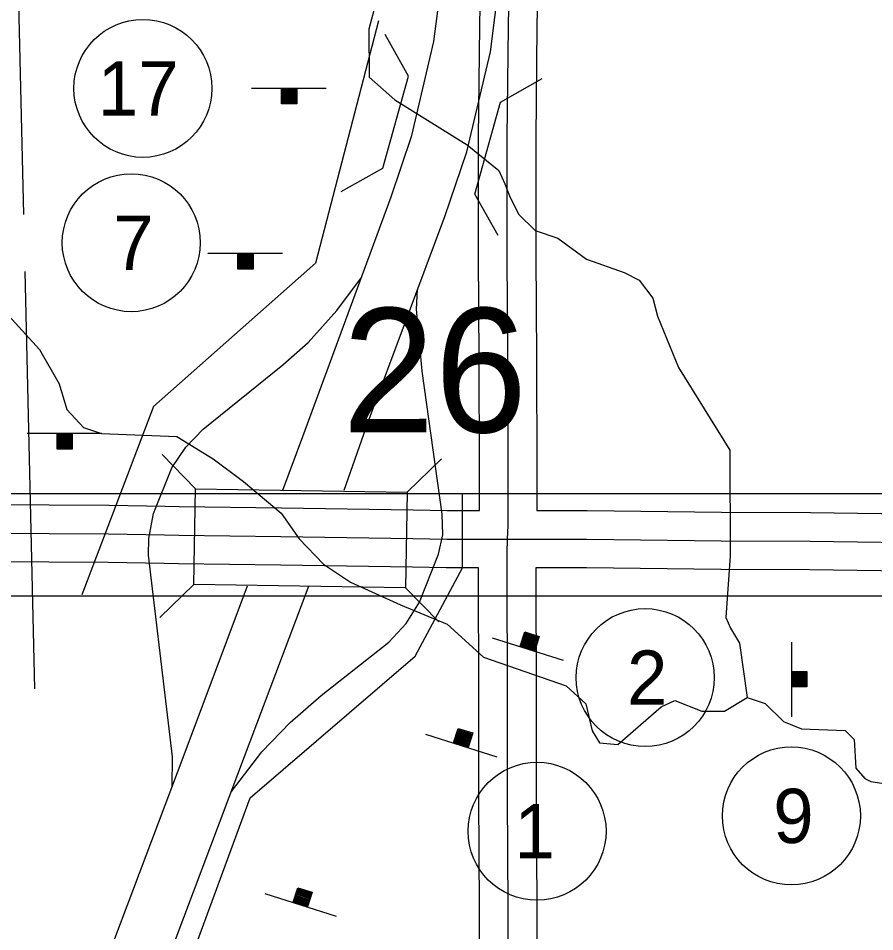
# Model space of a CAD drawing. Extents: x -2251611 to -2054719, y -2227156 to -2099355.
# Drawn here: x -2135345 to -2130609, y -2126976 to -2121927 of the extents above; entities that cross this region are included whole.
import ezdxf

# ---------------------------------------------------------------- set-up
doc = ezdxf.new("R2010")
doc.units = 0
for name, color, linetype in [('Default', 7, 'Continuous'), ('dsnTextFinalPlan', 7, 'Continuous'), ('dsnTextNote', 7, 'Continuous'), ('tdCoHydroRiver', 7, 'Continuous'), ('tdCoInt', 7, 'Continuous'), ('tdCoIntRamp', 7, 'Continuous'), ('tdCoSecRteBand', 7, 'Continuous'), ('tdCoSectLinePart', 7, 'Continuous'), ('tdCoSectNmbr', 7, 'Continuous'), ('tdCoStrucDivPri', 7, 'Continuous'), ('tdCoStrucNonDivPri', 7, 'Continuous'), ('tdCoSurfAsphalt', 7, 'Continuous'), ('tdCoSurfConc', 7, 'Continuous'), ('tdCoSurfEarth', 7, 'Continuous'), ('tdCoSurfGravel', 7, 'Continuous')]:
    doc.layers.add(name, color=color, linetype=linetype)

msp = doc.modelspace()

# ---------------------------------------------------------------- linework, layer by layer
at = {"layer": 'Default'}
for p, q in [((-2133352.6, -2121941.6), (-2133702.3, -2123281.5)), ((-2133702.3, -2123281.5), (-2134597.3, -2124073)), ((-2134597.3, -2124073), (-2134994.4, -2125113.5)), ((-2127105.2, -2124556.4), (-2138233.4, -2124556.4)), ((-2132888.1, -2124964.3), (-2132888.1, -2124556.4)), ((-2133150.5, -2125452.4), (-2132888.1, -2124964.3)), ((-2137523.9, -2125120.3), (-2127721.9, -2125120.3)), ((-2134063.3, -2126235.7), (-2133150.5, -2125452.4)), ((-2134962.1, -2128675.8), (-2134063.3, -2126235.7))]:
    msp.add_line(p, q, dxfattribs=at)
at = {"layer": 'dsnTextFinalPlan'}
for p, q in [((-2133642.7, -2122314.6), (-2134055.2, -2122314.6)), ((-2133889.4, -2122320.8), (-2133805.6, -2122320.8)), ((-2133805.6, -2122325), (-2133889.4, -2122325)), ((-2133889.4, -2122329), (-2133805.6, -2122329)), ((-2133805.6, -2122332.9), (-2133889.4, -2122332.9)), ((-2133889.4, -2122336.3), (-2133805.6, -2122336.3)), ((-2133805.6, -2122339.4), (-2133889.4, -2122339.4)), ((-2133889.4, -2122344.4), (-2133805.6, -2122344.4)), ((-2133805.6, -2122348.4), (-2133889.4, -2122348.4)), ((-2133889.4, -2122351.7), (-2133805.6, -2122351.5)), ((-2133805.6, -2122356.5), (-2133889.4, -2122356.5)), ((-2133889.4, -2122362.2), (-2133805.6, -2122362.2)), ((-2133805.6, -2122368.6), (-2133889.4, -2122368.6)), ((-2133889.4, -2122372), (-2133805.6, -2122371.7)), ((-2133805.6, -2122378.2), (-2133889.4, -2122378.5)), ((-2133889.4, -2122381.6), (-2133805.6, -2122381.6)), ((-2133805.6, -2122386.3), (-2133889.4, -2122386.3)), ((-2133889.4, -2122389.7), (-2133805.6, -2122389.7)), ((-2133805.6, -2122394.5), (-2133889.4, -2122394.5)), ((-2133883.9, -2123227.6), (-2134296.4, -2123227.6)), ((-2134130.6, -2123233.8), (-2134046.8, -2123233.8)), ((-2134046.8, -2123238), (-2134130.6, -2123238)), ((-2134130.6, -2123242), (-2134046.8, -2123242)), ((-2134046.8, -2123245.9), (-2134130.6, -2123245.9)), ((-2134130.6, -2123249.3), (-2134046.8, -2123249.3)), ((-2134046.8, -2123252.4), (-2134130.6, -2123252.4)), ((-2134130.6, -2123257.4), (-2134046.8, -2123257.4)), ((-2134046.8, -2123261.4), (-2134130.6, -2123261.4)), ((-2134130.6, -2123264.7), (-2134046.8, -2123264.5)), ((-2134046.8, -2123269.5), (-2134130.6, -2123269.5)), ((-2134130.6, -2123275.2), (-2134046.8, -2123275.2)), ((-2134046.8, -2123281.6), (-2134130.6, -2123281.6)), ((-2134130.6, -2123285), (-2134046.8, -2123284.7)), ((-2134046.8, -2123291.2), (-2134130.6, -2123291.5)), ((-2134130.6, -2123294.6), (-2134046.8, -2123294.6)), ((-2134046.8, -2123299.3), (-2134130.6, -2123299.3)), ((-2134130.6, -2123302.7), (-2134046.8, -2123302.7)), ((-2134046.8, -2123307.5), (-2134130.6, -2123307.5)), ((-2134884.3, -2124222.9), (-2135296.8, -2124222.9)), ((-2135131, -2124229.1), (-2135047.2, -2124229.1)), ((-2135047.2, -2124233.4), (-2135131, -2124233.4)), ((-2135131, -2124237.3), (-2135047.2, -2124237.3)), ((-2135047.2, -2124241.2), (-2135131, -2124241.2)), ((-2135131, -2124244.6), (-2135047.2, -2124244.6)), ((-2135047.2, -2124247.7), (-2135131, -2124247.7)), ((-2135131, -2124252.8), (-2135047.2, -2124252.8)), ((-2135047.2, -2124256.7), (-2135131, -2124256.7)), ((-2135131, -2124260.1), (-2135047.2, -2124259.8)), ((-2135047.2, -2124264.9), (-2135131, -2124264.9)), ((-2135131, -2124270.5), (-2135047.2, -2124270.5)), ((-2135047.2, -2124277), (-2135131, -2124277)), ((-2135131, -2124280.3), (-2135047.2, -2124280)), ((-2135047.2, -2124286.5), (-2135131, -2124286.8)), ((-2135131, -2124289.9), (-2135047.2, -2124289.9)), ((-2135047.2, -2124294.7), (-2135131, -2124294.7)), ((-2135131, -2124298), (-2135047.2, -2124298)), ((-2135047.2, -2124302.8), (-2135131, -2124302.8)), ((-2132725.2, -2125350.8), (-2132332, -2125475.4)), ((-2132557.2, -2125360), (-2132477.3, -2125385.4)), ((-2132475.6, -2125380), (-2132555.5, -2125354.7)), ((-2132553.5, -2125348.5), (-2132473.6, -2125373.8)), ((-2132472.6, -2125370.6), (-2132552.6, -2125345.6)), ((-2132550.7, -2125339.4), (-2132470.7, -2125364.5)), ((-2132469.7, -2125361.5), (-2132549.6, -2125336.2)), ((-2132548.2, -2125331.6), (-2132468.3, -2125357)), ((-2132467.3, -2125353.7), (-2132547.2, -2125328.4)), ((-2132545.7, -2125323.8), (-2132465.8, -2125349.2)), ((-2132488.1, -2125419.4), (-2132568, -2125394.1)), ((-2132566.7, -2125390.1), (-2132486.8, -2125415.4)), ((-2132485.6, -2125411.6), (-2132565.5, -2125386.3)), ((-2132564.3, -2125382.6), (-2132484.4, -2125407.9)), ((-2132483.4, -2125404.7), (-2132563.3, -2125379.3)), ((-2132562.4, -2125376.4), (-2132482.5, -2125401.7)), ((-2132481, -2125396.9), (-2132560.9, -2125371.6)), ((-2132559.7, -2125367.8), (-2132479.8, -2125393.1)), ((-2132478.7, -2125389.9), (-2132558.7, -2125364.9)), ((-2131069.9, -2125376.2), (-2131069.9, -2125788.7)), ((-2131063.7, -2125623), (-2131063.7, -2125539.1)), ((-2131059.4, -2125539.1), (-2131059.4, -2125623)), ((-2131055.5, -2125623), (-2131055.5, -2125539.1)), ((-2131051.6, -2125539.1), (-2131051.6, -2125623)), ((-2131048.2, -2125623), (-2131048.2, -2125539.1)), ((-2131045.1, -2125539.1), (-2131045.1, -2125623)), ((-2131040.1, -2125623), (-2131040.1, -2125539.1)), ((-2131036.1, -2125539.1), (-2131036.1, -2125623)), ((-2131032.7, -2125623), (-2131033, -2125539.1)), ((-2131027.9, -2125539.1), (-2131027.9, -2125623)), ((-2131022.3, -2125623), (-2131022.3, -2125539.1)), ((-2131015.9, -2125539.1), (-2131015.9, -2125623)), ((-2131012.5, -2125623), (-2131012.8, -2125539.1)), ((-2131006.3, -2125539.1), (-2131006, -2125623)), ((-2131002.9, -2125623), (-2131002.9, -2125539.1)), ((-2130998.1, -2125539.1), (-2130998.1, -2125623)), ((-2130994.8, -2125623), (-2130994.8, -2125539.1)), ((-2130990, -2125539.1), (-2130990, -2125623)), ((-2132915.9, -2125865.7), (-2132836, -2125891.1)), ((-2132835, -2125887.8), (-2132914.9, -2125862.5)), ((-2132913.4, -2125858), (-2132833.5, -2125883.3)), ((-2133092.9, -2125884.9), (-2132699.7, -2126009.5)), ((-2132932, -2125916.7), (-2132852.1, -2125942)), ((-2132851.1, -2125938.8), (-2132931, -2125913.4)), ((-2132930.1, -2125910.5), (-2132850.2, -2125935.8)), ((-2132848.7, -2125931), (-2132928.6, -2125905.7)), ((-2132927.4, -2125901.9), (-2132847.5, -2125927.3)), ((-2132846.4, -2125924), (-2132926.4, -2125899)), ((-2132924.9, -2125894.1), (-2132845, -2125919.5)), ((-2132843.3, -2125914.1), (-2132923.2, -2125888.8)), ((-2132921.2, -2125882.6), (-2132841.3, -2125907.9)), ((-2132840.3, -2125904.7), (-2132920.3, -2125879.7)), ((-2132918.4, -2125873.5), (-2132838.4, -2125898.6)), ((-2132837.4, -2125895.6), (-2132917.3, -2125870.3)), ((-2132855.8, -2125953.5), (-2132935.7, -2125928.2)), ((-2132934.4, -2125924.2), (-2132854.5, -2125949.5)), ((-2132853.3, -2125945.8), (-2132933.2, -2125920.4)), ((-2133980.9, -2126765.4), (-2133587.7, -2126890.1)), ((-2133812.9, -2126774.7), (-2133733, -2126800)), ((-2133731.3, -2126794.7), (-2133811.2, -2126769.3)), ((-2133809.2, -2126763.2), (-2133729.3, -2126788.5)), ((-2133728.3, -2126785.3), (-2133808.3, -2126760.2)), ((-2133806.4, -2126754), (-2133726.4, -2126779.1)), ((-2133725.4, -2126776.2), (-2133805.3, -2126750.8)), ((-2133803.9, -2126746.3), (-2133724, -2126771.6)), ((-2133723, -2126768.4), (-2133802.9, -2126743.1)), ((-2133801.4, -2126738.5), (-2133721.5, -2126763.8)), ((-2133743.8, -2126834.1), (-2133823.7, -2126808.8)), ((-2133822.4, -2126804.7), (-2133742.5, -2126830.1)), ((-2133741.3, -2126826.3), (-2133821.2, -2126801)), ((-2133820, -2126797.2), (-2133740.1, -2126822.5)), ((-2133739.1, -2126819.3), (-2133819, -2126794)), ((-2133818.1, -2126791.1), (-2133738.2, -2126816.4)), ((-2133736.7, -2126811.6), (-2133816.6, -2126786.2)), ((-2133815.4, -2126782.5), (-2133735.5, -2126807.8)), ((-2133734.4, -2126804.6), (-2133814.4, -2126779.5))]:
    msp.add_line(p, q, dxfattribs=at)
for points in [[(-2133889.4, -2122316), (-2133805.1, -2122316), (-2133805.1, -2122400.4), (-2133889.4, -2122400.4)], [(-2134130.6, -2123229), (-2134046.3, -2123229), (-2134046.3, -2123313.4), (-2134130.6, -2123313.4)], [(-2135131, -2124224.4), (-2135046.6, -2124224.4), (-2135046.6, -2124308.7), (-2135131, -2124308.7)], [(-2132489.5, -2125424), (-2132570, -2125398.5), (-2132544.5, -2125318), (-2132464, -2125343.5)], [(-2131068.4, -2125623), (-2131068.4, -2125538.6), (-2130984.1, -2125538.6), (-2130984.1, -2125623)], [(-2132857.2, -2125958.1), (-2132937.7, -2125932.6), (-2132912.2, -2125852.1), (-2132831.7, -2125877.7)], [(-2133745.2, -2126838.6), (-2133825.7, -2126813.1), (-2133800.2, -2126732.7), (-2133719.7, -2126758.2)]]:
    msp.add_lwpolyline(points, close=True, dxfattribs=at)
at = {"layer": 'dsnTextNote'}
for centre in [(-2134656.1, -2122314.6), (-2134720.4, -2123167.8), (-2131878.4, -2125571.6), (-2131069.9, -2126335.9), (-2132476.4, -2126420.8)]:
    msp.add_circle(centre, 381.4, dxfattribs=at)
at = {"layer": 'tdCoHydroRiver'}
for points in [[(-2133365.1, -2121828.1), (-2133406.4, -2121986.5), (-2133405.7, -2122253.1), (-2133263.8, -2122377.8), (-2132863.3, -2122626.8), (-2132688, -2122768.1), (-2132654.5, -2122842.9), (-2132629.3, -2122909.5), (-2132579.1, -2123009.4), (-2132487.2, -2123100.9), (-2132362.1, -2123142.2), (-2132203.5, -2123258.5), (-2131995.1, -2123333), (-2131911.7, -2123374.5), (-2131836.4, -2123474.3), (-2131811.2, -2123574.2), (-2131693.9, -2123857.2), (-2131409.5, -2124314.9), (-2131408.1, -2124898.1), (-2131432.3, -2125239.8), (-2131407.2, -2125298), (-2131357, -2125381.2), (-2131314.6, -2125681.1)], [(-2135494.3, -2123466.1), (-2135227, -2123757.1), (-2135118.2, -2123948.5), (-2135076.2, -2124090.1), (-2134984.3, -2124189.8), (-2134884.3, -2124222.9), (-2134467.6, -2124238.6), (-2134267.4, -2124363.1), (-2134100.4, -2124487.7), (-2133891.7, -2124662.2), (-2133791.4, -2124803.6), (-2133657.8, -2124945), (-2133507.5, -2125044.6), (-2133232.3, -2125169), (-2132973.7, -2125276.7), (-2132773.3, -2125459.5), (-2132314.7, -2125616.8), (-2132206.1, -2125716.5), (-2132172.4, -2125866.4), (-2132130.6, -2125932.9), (-2132030.6, -2125941.1), (-2131789.4, -2125732.2), (-2131714.6, -2125698.7), (-2131564.4, -2125756.7), (-2131439.4, -2125756.4), (-2131314.6, -2125681.1)], [(-2131314.6, -2125681.1), (-2131214.6, -2125714.2), (-2131114.4, -2125813.9), (-2131014.3, -2125855.4), (-2130772.6, -2125863.1), (-2130722.5, -2125913), (-2130713.8, -2126071.3), (-2130663.7, -2126129.5), (-2130630.3, -2126146.1), (-2130522, -2126162.5), (-2130455.4, -2126104), (-2130397.2, -2126070.6), (-2130313.7, -2126128.7), (-2130321.5, -2126353.7), (-2130296.5, -2126378.6), (-2130296.4, -2126412), (-2130263, -2126453.5), (-2130096.1, -2126553.1), (-2130012.7, -2126569.6), (-2129846.2, -2126519.2), (-2129662.7, -2126602.1), (-2129620.9, -2126643.7), (-2129603.9, -2126785.3), (-2129778.4, -2126977.3)]]:
    msp.add_lwpolyline(points, dxfattribs=at)
at = {"layer": 'tdCoInt'}
for points in [[(-2133881.8, -2124535.9), (-2133771.2, -2124239.6), (-2133284, -2122914.7), (-2133169.3, -2122575.3), (-2133046.5, -2122055.7), (-2132978.9, -2121530.2), (-2132959.2, -2121137.6), (-2132961, -2118109.7)], [(-2133543.6, -2124536.1), (-2133411.1, -2124158.6), (-2132986.2, -2123022.8), (-2132865.5, -2122665.2), (-2132734.6, -2122112.3), (-2132663, -2121556), (-2132642.4, -2121146.1), (-2132644.2, -2118109.7)], [(-2135592.8, -2137726.6), (-2135583.3, -2135364.8), (-2135600, -2134511.1), (-2135597.6, -2130377.8), (-2135576.2, -2129678.1), (-2135530.5, -2129293.5), (-2135472.8, -2128971.6), (-2135331.5, -2128427.1), (-2135168.7, -2127959.9), (-2134428.5, -2125998.1), (-2134077.2, -2125063.6)], [(-2135275.9, -2137726.7), (-2135266.4, -2135362.5), (-2135283.2, -2134507.8), (-2135280.8, -2130380.1), (-2135260.2, -2129703.7), (-2135216.9, -2129339.5), (-2135162.2, -2129034.2), (-2135027.4, -2128516.2), (-2134871.9, -2128070.7), (-2134130.5, -2126105.6), (-2133742.1, -2125075.1), (-2133739, -2125066.2)]]:
    msp.add_lwpolyline(points, dxfattribs=at)
at = {"layer": 'tdCoIntRamp'}
for points in [[(-2134495.1, -2126174.5), (-2134492.7, -2126009.7), (-2134625.1, -2124894.5), (-2134623.1, -2124801.8), (-2134597.3, -2124665.2), (-2134496.5, -2124412.8), (-2134419.1, -2124297.5), (-2134322.5, -2124197.8), (-2133882.8, -2123843.3), (-2133742.9, -2123719.4), (-2133583.4, -2123542), (-2133448, -2123360.8)], [(-2134166.7, -2126201.4), (-2133997.9, -2125982.5), (-2133842.2, -2125820.6), (-2133670.1, -2125670), (-2133295.3, -2125376.3), (-2133200.7, -2125272.8), (-2133125.7, -2125154.4), (-2133021.9, -2124889.7), (-2132997.5, -2124782.2), (-2133000.7, -2124668.3), (-2133111.4, -2123877.3), (-2133143.9, -2123535.5), (-2133137.2, -2123426.5)]]:
    msp.add_lwpolyline(points, dxfattribs=at)
at = {"layer": 'tdCoSecRteBand'}
for points in [[(-2132794.9, -2124647.5), (-2132794.9, -2124633.3), (-2132794.9, -2124417.6), (-2132796.2, -2123810.1), (-2132800.1, -2123238.9), (-2132800.1, -2123238.3), (-2132800.1, -2123237.8), (-2132800.1, -2122586.7), (-2132800.1, -2122585.9), (-2132800.1, -2122585.1), (-2132793.6, -2121970.5), (-2132793.6, -2121969.9), (-2132793.6, -2121969.3), (-2132781.8, -2121315.7)], [(-2132465.1, -2121321.7), (-2132476.8, -2121974.4), (-2132483.3, -2122587.6), (-2132483.3, -2123237.2), (-2132479.4, -2123808.3), (-2132479.4, -2123808.7), (-2132479.4, -2123809), (-2132478.1, -2124417.1), (-2132478.1, -2124417.3), (-2132478.1, -2124417.5), (-2132478.1, -2124633.3), (-2132478.1, -2124647.7), (-2132366.6, -2124647.7), (-2132201.4, -2124647.8), (-2132200.4, -2124647.8), (-2132199.5, -2124647.8), (-2131456.6, -2124656.9), (-2130964.9, -2124659.5), (-2130964.3, -2124659.5), (-2130963.7, -2124659.5), (-2130050.5, -2124671.2), (-2129005, -2124673.8)], [(-2135679.7, -2124613.9), (-2135173.5, -2124616.9), (-2134844.8, -2124618.8), (-2134844, -2124618.8), (-2134843.1, -2124618.8), (-2134533.4, -2124624), (-2134455.5, -2124625.1), (-2134454.9, -2124625.2), (-2134454.9, -2124625.2), (-2134454.8, -2124625.2), (-2133890.4, -2124633.2), (-2133890.3, -2124633.2), (-2133890.2, -2124633.2), (-2133160.6, -2124644.6), (-2132974.7, -2124647.5), (-2132794.9, -2124647.5)], [(-2132793.6, -2127488.1), (-2132794.9, -2126842.4), (-2132797.5, -2126234.5), (-2132797.5, -2126234.4), (-2132797.5, -2126234.2), (-2132798.8, -2125635.2), (-2132800.1, -2125019.4), (-2132800.1, -2125019.2), (-2132800.1, -2125019), (-2132800.1, -2124964.3), (-2132976, -2124964.3), (-2132977.2, -2124964.3), (-2132978.4, -2124964.2), (-2133165.5, -2124961.3), (-2133895, -2124949.9), (-2134459.2, -2124941.9), (-2134459.8, -2124941.9), (-2134459.9, -2124941.9), (-2134459.9, -2124941.9), (-2134538.1, -2124940.8), (-2134538.3, -2124940.8), (-2134538.5, -2124940.8), (-2134847.6, -2124935.6), (-2135175.4, -2124933.7), (-2135681.5, -2124930.7)], [(-2130053.7, -2124988), (-2130967.2, -2124976.3), (-2131458.8, -2124973.7), (-2131459.3, -2124973.7), (-2131459.9, -2124973.7), (-2132202.4, -2124964.6), (-2132366.7, -2124964.5), (-2132480.8, -2124964.5), (-2132483.3, -2124964.5), (-2132483.3, -2125018.9), (-2132482, -2125634.6), (-2132480.7, -2126233.3), (-2132478.1, -2126841.3), (-2132478.1, -2126841.4), (-2132478.1, -2126841.6), (-2132476.8, -2127487.3)]]:
    msp.add_lwpolyline(points, dxfattribs=at)
at = {"layer": 'tdCoSectLinePart'}
for points in [[(-2135374.5, -2120517.6), (-2135316.4, -2123011.2)], [(-2135309, -2123327), (-2135255.2, -2125633.5)]]:
    msp.add_lwpolyline(points, dxfattribs=at)
at = {"layer": 'tdCoStrucDivPri'}
for points in [[(-2133559.8, -2122885.3), (-2133329.6, -2122755.9), (-2133187.1, -2122247.5), (-2133316.5, -2122017.4)], [(-2132691.9, -2123128.6), (-2132821.3, -2122898.5), (-2132678.7, -2122390.1), (-2132448.6, -2122260.7)]]:
    msp.add_lwpolyline(points, dxfattribs=at)
at = {"layer": 'tdCoStrucNonDivPri'}
for p, q in [((-2134365.4, -2124528.3), (-2134549.2, -2124338.8)), ((-2133195, -2124546.6), (-2133005.4, -2124362.9)), ((-2134373.7, -2125056.3), (-2134563.2, -2125240)), ((-2133203.2, -2125074.6), (-2133019.5, -2125264.1))]:
    msp.add_line(p, q, dxfattribs=at)
msp.add_lwpolyline([(-2134365.4, -2124528.3), (-2133195, -2124546.6), (-2133203.2, -2125074.6), (-2134373.7, -2125056.3)], close=True, dxfattribs=at)
at = {"layer": 'tdCoSurfAsphalt'}
for points in [[(-2143114.6, -2124764.5), (-2142603.4, -2124765.6), (-2141593.3, -2124764.5), (-2140911.1, -2124761.9), (-2139929.3, -2124754.1), (-2138864.2, -2124752.8), (-2138200.1, -2124755.4), (-2137857.2, -2124757.9), (-2137490.5, -2124760.6), (-2136678, -2124767.1), (-2135680.6, -2124772.3), (-2135174.5, -2124775.3)], [(-2135174.5, -2124775.3), (-2134845.8, -2124777.2), (-2134535.9, -2124782.4), (-2134457.7, -2124783.5), (-2134457.1, -2124783.5)], [(-2132366.6, -2124806.1), (-2132201.4, -2124806.2), (-2131457.9, -2124815.3), (-2130965.8, -2124817.9), (-2130051.7, -2124829.6), (-2129004.8, -2124832.2), (-2128055.6, -2124828.3), (-2127329.6, -2124825.1)]]:
    msp.add_lwpolyline(points, dxfattribs=at)
at = {"layer": 'tdCoSurfConc'}
msp.add_lwpolyline([(-2134457.1, -2124783.5), (-2133892.6, -2124791.5), (-2133163, -2124802.9), (-2132976, -2124805.9), (-2132639.1, -2124806), (-2132366.6, -2124806.1)], dxfattribs=at)
at = {"layer": 'tdCoSurfEarth'}
msp.add_lwpolyline([(-2132636.5, -2124633.3), (-2132636.5, -2124417.5), (-2132637.8, -2123809.4), (-2132641.7, -2123237.8), (-2132641.7, -2122586.7), (-2132635.2, -2121972.1), (-2132623.5, -2121318.5), (-2132607.8, -2120620.6), (-2132594.8, -2120016.4), (-2132584.4, -2119525.5), (-2132582.1, -2119515.9), (-2132577.8, -2119506.9), (-2132571.8, -2119499), (-2132570.4, -2119497.8)], dxfattribs=at)
at = {"layer": 'tdCoSurfGravel'}
for points in [[(-2132639.1, -2124806), (-2132636.5, -2124730), (-2132636.5, -2124633.3)], [(-2132635.8, -2130092.9), (-2132635.8, -2130087.1), (-2132635.2, -2129973.4), (-2132635.2, -2129364.1), (-2132636.5, -2128756), (-2132632.6, -2128157), (-2132635.2, -2127487.8), (-2132636.5, -2126841.9), (-2132639.1, -2126233.9), (-2132640.4, -2125634.9), (-2132641.7, -2125019), (-2132641.7, -2124881), (-2132639.1, -2124806)]]:
    msp.add_lwpolyline(points, dxfattribs=at)

# ---------------------------------------------------------------- texts
at = {"layer": 'dsnTextNote'}
for s, p in [('17', (-2134905.2, -2122464.6)), ('7', (-2134820.6, -2123317.8)), ('2', (-2131978.7, -2125721.6)), ('9', (-2131170.1, -2126485.9)), ('1', (-2132601.4, -2126570.8))]:
    msp.add_text(s, height=300, dxfattribs=at).set_placement(p)
at = {"layer": 'tdCoSectNmbr'}
msp.add_text('26', height=686.4, rotation=0.0203, dxfattribs=at).set_placement((-2133552.6, -2124215.9))

doc.saveas('drawing.dxf')
